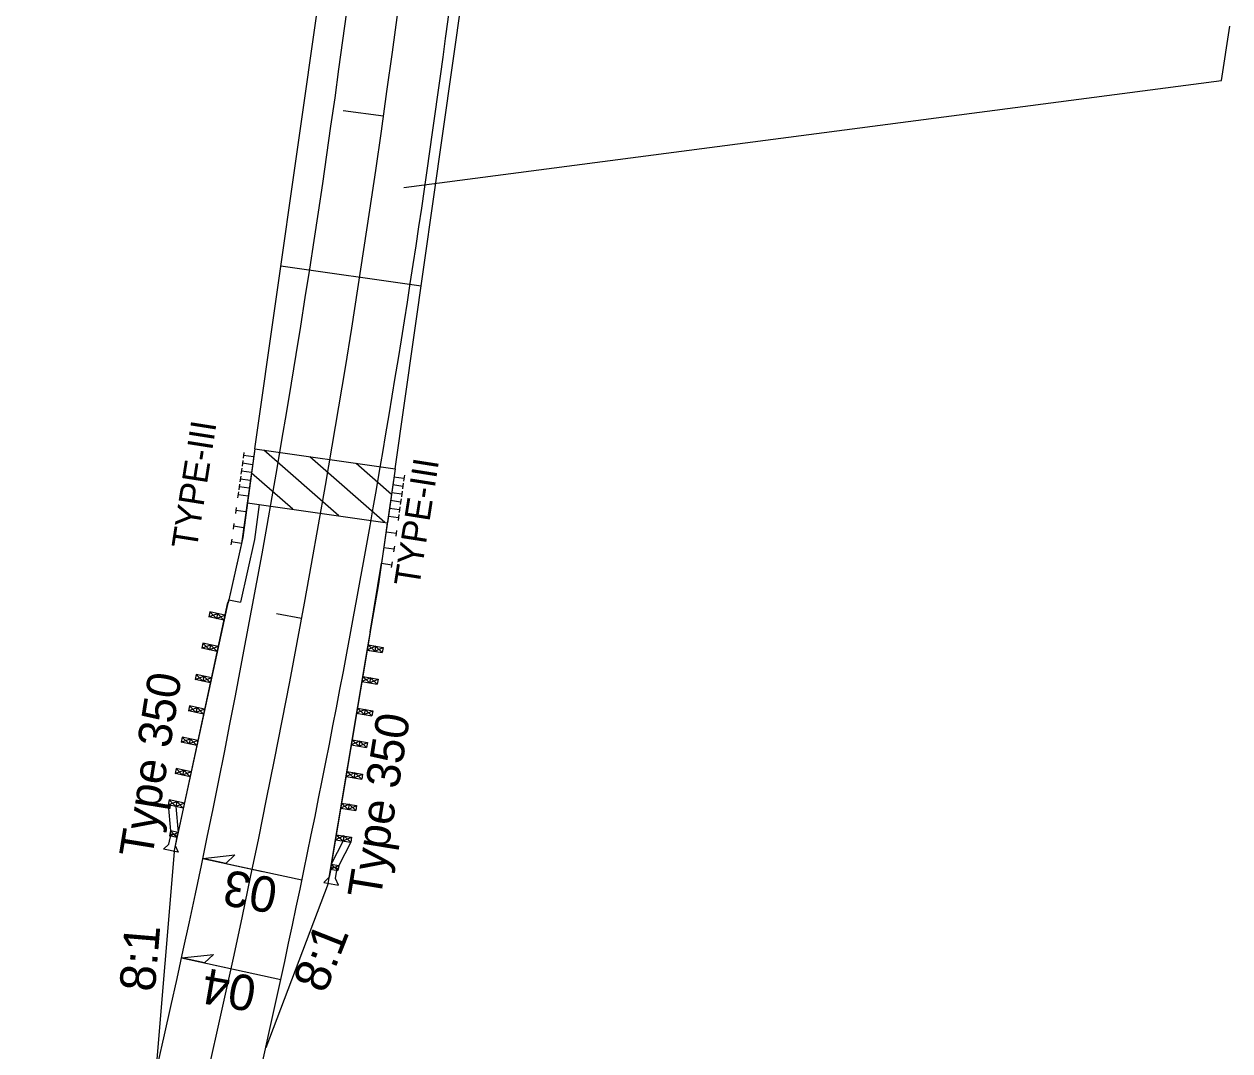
# Model space of a CAD drawing. Extents: x 1698814 to 1699654, y 708133 to 709468.
# Drawn here: x 1699331.8 to 1699568.8, y 708558.2 to 708760.1 of the extents above; entities that cross this region are included whole.
import ezdxf

# ---------------------------------------------------------------- set-up
doc = ezdxf.new("R2010")
doc.units = 0
for name, color, linetype in [('Prop Approach Slab', 7, 'Continuous'), ('Prop Approach Slab Hatching', 7, 'Continuous'), ('Prop Conc Shoulder Berm Gutter', 7, 'Continuous'), ('Prop Dimension', 7, 'Continuous'), ('Prop EOT', 7, 'Continuous'), ('Prop Guardrail', 7, 'Continuous'), ('Prop Guardrail Anchor Unit CELL', 7, 'Continuous'), ('Prop Horizontal Alignment', 7, 'Continuous'), ('Prop Horizontal Alignment Tick Large', 7, 'Continuous'), ('Prop Horizontal Alignment Tick Small', 7, 'Continuous'), ('Prop Paved Shoulder', 7, 'Continuous'), ('Prop Roadway Bridge', 7, 'Continuous'), ('Prop Structure Anchor Unit CELL', 7, 'Continuous'), ('Prop Superelevation  Arrow CELL', 7, 'Continuous'), ('Prop Superelevation Label', 7, 'Continuous')]:
    doc.layers.add(name, color=color, linetype=linetype)

msp = doc.modelspace()

# ---------------------------------------------------------------- linework, layer by layer
at = {"layer": 'Prop Approach Slab'}
for p, q in [((1699377.2, 708676.53), (1699375.7, 708665.94)), ((1699404.76, 708672.62), (1699403.26, 708662.03)), ((1699375.7, 708665.94), (1699403.26, 708662.03))]:
    msp.add_line(p, q, dxfattribs=at)
at = {"layer": 'Prop Approach Slab Hatching'}
for p, q in [((1699393.66, 708663.39), (1699378.96, 708676.28)), ((1699402.72, 708662.11), (1699388.01, 708674.99)), ((1699404.05, 708667.59), (1699397.06, 708673.71)), ((1699384.61, 708664.68), (1699376.52, 708671.76))]:
    msp.add_line(p, q, dxfattribs=at)
at = {"layer": 'Prop Conc Shoulder Berm Gutter'}
for p, q in [((1699375.73, 708665.94), (1699374.79, 708659.14)), ((1699402.98, 708660.05), (1699403.26, 708662.03)), ((1699374.79, 708659.14), (1699372.08, 708646.9)), ((1699372.08, 708646.9), (1699372.05, 708646.78))]:
    msp.add_line(p, q, dxfattribs=at)
at = {"layer": 'Prop Dimension'}
for p, q in [((1699567.1, 708748.96), (1699568.78, 708759.65)), ((1699406.45, 708727.92), (1699567.1, 708748.96))]:
    msp.add_line(p, q, dxfattribs=at)
at = {"layer": 'Prop EOT'}
for centre, radius, start, end in [((1697124.94, 709062.69), 2310, 350.26654, 356.20849), ((1697132.82, 709061.2), 2282.04, 344.49766, 353.61848), ((1697124.94, 709062.69), 2310, 344.49666, 350.26654)]:
    msp.add_arc(centre, radius, start, end, dxfattribs=at)
at = {"layer": 'Prop Guardrail'}
for p, q in [((1699374.53, 708657.97), (1699371.9, 708646.32)), ((1699399.84, 708640.51), (1699402.09, 708654.06))]:
    msp.add_line(p, q, dxfattribs=at)
at = {"layer": 'Prop Guardrail Anchor Unit CELL'}
for p, q in [((1699371.83, 708646.34), (1699361.98, 708600.64)), ((1699368.36, 708644.49), (1699368.15, 708643.51)), ((1699368.15, 708643.51), (1699369.83, 708644.17)), ((1699371.29, 708643.85), (1699368.36, 708644.49)), ((1699369.62, 708643.19), (1699368.36, 708644.49)), ((1699369.83, 708644.17), (1699369.62, 708643.19)), ((1699369.62, 708643.19), (1699371.29, 708643.85)), ((1699369.83, 708644.17), (1699371.08, 708642.88)), ((1699371.29, 708643.85), (1699371.08, 708642.88)), ((1699371.08, 708642.88), (1699368.15, 708643.51)), ((1699371.08, 708642.88), (1699369.62, 708643.19)), ((1699399.84, 708640.51), (1699392.11, 708594.4)), ((1699366.98, 708638.34), (1699366.77, 708637.36)), ((1699366.77, 708637.36), (1699368.47, 708638.02)), ((1699369.76, 708636.72), (1699366.77, 708637.36)), ((1699369.97, 708637.69), (1699366.98, 708638.34)), ((1699368.26, 708637.04), (1699366.98, 708638.34)), ((1699368.47, 708638.02), (1699368.26, 708637.04)), ((1699369.97, 708637.69), (1699368.26, 708637.04)), ((1699368.47, 708638.02), (1699369.76, 708636.72)), ((1699399.42, 708638), (1699399.26, 708637.01)), ((1699400.9, 708637.75), (1699399.26, 708637.01)), ((1699399.26, 708637.01), (1699402.21, 708636.52)), ((1699399.26, 708637.01), (1699400.74, 708636.77)), ((1699399.42, 708638), (1699402.38, 708637.5)), ((1699400.74, 708636.77), (1699399.42, 708638)), ((1699400.9, 708637.75), (1699400.74, 708636.77)), ((1699400.74, 708636.77), (1699402.38, 708637.5)), ((1699402.21, 708636.52), (1699400.9, 708637.75)), ((1699402.38, 708637.5), (1699402.21, 708636.52)), ((1699365.66, 708632.18), (1699365.45, 708631.2)), ((1699365.45, 708631.2), (1699367.15, 708631.86)), ((1699368.64, 708631.53), (1699365.66, 708632.18)), ((1699366.94, 708630.88), (1699365.66, 708632.18)), ((1699367.15, 708631.86), (1699366.94, 708630.88)), ((1699367.15, 708631.86), (1699368.43, 708630.56)), ((1699368.43, 708630.56), (1699365.45, 708631.2)), ((1699368.64, 708631.53), (1699366.94, 708630.88)), ((1699399.89, 708631.53), (1699398.21, 708630.8)), ((1699398.21, 708630.8), (1699401.23, 708630.29)), ((1699398.38, 708631.79), (1699401.39, 708631.28)), ((1699398.38, 708631.79), (1699399.72, 708630.55)), ((1699399.89, 708631.53), (1699399.72, 708630.55)), ((1699399.72, 708630.55), (1699401.39, 708631.28)), ((1699401.23, 708630.29), (1699399.89, 708631.53)), ((1699401.39, 708631.28), (1699401.23, 708630.29)), ((1699364.34, 708626.01), (1699364.13, 708625.04)), ((1699364.13, 708625.04), (1699365.83, 708625.69)), ((1699367.1, 708624.4), (1699364.13, 708625.04)), ((1699367.31, 708625.37), (1699364.34, 708626.01)), ((1699365.61, 708624.72), (1699364.34, 708626.01)), ((1699365.83, 708625.69), (1699365.61, 708624.72)), ((1699367.31, 708625.37), (1699365.61, 708624.72)), ((1699365.83, 708625.69), (1699367.1, 708624.4)), ((1699367.31, 708625.37), (1699367.1, 708624.4)), ((1699398.84, 708625.32), (1699397.17, 708624.58)), ((1699397.34, 708625.57), (1699400.34, 708625.07)), ((1699397.34, 708625.57), (1699398.68, 708624.33)), ((1699398.84, 708625.32), (1699398.68, 708624.33)), ((1699398.68, 708624.33), (1699400.34, 708625.07)), ((1699400.18, 708624.08), (1699398.84, 708625.32)), ((1699400.34, 708625.07), (1699400.18, 708624.08)), ((1699397.17, 708624.58), (1699400.18, 708624.08)), ((1699362.91, 708619.88), (1699362.7, 708618.9)), ((1699362.7, 708618.9), (1699364.45, 708619.55)), ((1699365.77, 708618.24), (1699362.7, 708618.9)), ((1699365.98, 708619.22), (1699362.91, 708619.88)), ((1699364.24, 708618.57), (1699362.91, 708619.88)), ((1699364.45, 708619.55), (1699364.24, 708618.57)), ((1699365.98, 708619.22), (1699364.24, 708618.57)), ((1699364.45, 708619.55), (1699365.77, 708618.24)), ((1699396.3, 708619.36), (1699396.13, 708618.37)), ((1699397.79, 708619.1), (1699396.13, 708618.37)), ((1699396.13, 708618.37), (1699399.13, 708617.87)), ((1699396.3, 708619.36), (1699399.29, 708618.85)), ((1699396.3, 708619.36), (1699397.63, 708618.12)), ((1699397.79, 708619.1), (1699397.63, 708618.12)), ((1699397.63, 708618.12), (1699399.29, 708618.85)), ((1699399.13, 708617.87), (1699397.79, 708619.1)), ((1699399.29, 708618.85), (1699399.13, 708617.87)), ((1699361.72, 708613.69), (1699361.51, 708612.71)), ((1699361.51, 708612.71), (1699363.19, 708613.37)), ((1699364.65, 708613.06), (1699361.72, 708613.69)), ((1699362.98, 708612.39), (1699361.72, 708613.69)), ((1699363.19, 708613.37), (1699362.98, 708612.39)), ((1699364.65, 708613.06), (1699362.98, 708612.39)), ((1699363.19, 708613.37), (1699364.44, 708612.08)), ((1699395.26, 708613.14), (1699398.35, 708612.62)), ((1699395.26, 708613.14), (1699396.64, 708611.9)), ((1699364.44, 708612.08), (1699361.51, 708612.71)), ((1699396.8, 708612.88), (1699395.09, 708612.16)), ((1699395.09, 708612.16), (1699398.18, 708611.64)), ((1699396.8, 708612.88), (1699396.64, 708611.9)), ((1699396.64, 708611.9), (1699398.35, 708612.62)), ((1699398.18, 708611.64), (1699396.8, 708612.88)), ((1699398.35, 708612.62), (1699398.18, 708611.64)), ((1699360.33, 708607.54), (1699360.12, 708606.56)), ((1699360.12, 708606.56), (1699361.83, 708607.22)), ((1699363.12, 708605.92), (1699360.12, 708606.56)), ((1699360.12, 708606.56), (1699360.62, 708601.44)), ((1699363.33, 708606.9), (1699360.33, 708607.54)), ((1699361.62, 708606.24), (1699360.33, 708607.54)), ((1699361.83, 708607.22), (1699361.62, 708606.24)), ((1699363.33, 708606.9), (1699361.62, 708606.24)), ((1699361.62, 708606.24), (1699362.08, 708601.13)), ((1699361.83, 708607.22), (1699363.12, 708605.92)), ((1699395.69, 708606.68), (1699394.05, 708605.94)), ((1699394.05, 708605.94), (1699397.01, 708605.44)), ((1699394.21, 708606.93), (1699397.17, 708606.43)), ((1699394.21, 708606.93), (1699395.53, 708605.69)), ((1699395.69, 708606.68), (1699395.53, 708605.69)), ((1699395.53, 708605.69), (1699397.17, 708606.43)), ((1699397.01, 708605.44), (1699395.69, 708606.68)), ((1699397.17, 708606.43), (1699397.01, 708605.44)), ((1699360.62, 708601.44), (1699360.41, 708600.47)), ((1699360.41, 708600.47), (1699362.08, 708601.13)), ((1699360.62, 708601.44), (1699360.51, 708600.95)), ((1699362.08, 708601.13), (1699360.62, 708601.44)), ((1699361.87, 708600.15), (1699360.62, 708601.44)), ((1699359.23, 708597.86), (1699360.3, 708598.85)), ((1699360.3, 708598.85), (1699360.7, 708600.86)), ((1699361.87, 708600.15), (1699360.41, 708600.47)), ((1699360.7, 708600.86), (1699361.3, 708600.74)), ((1699361.3, 708600.74), (1699361.9, 708600.62)), ((1699361.9, 708600.62), (1699361.5, 708598.61)), ((1699394.52, 708599.47), (1699392.2, 708594.89)), ((1699394.68, 708600.46), (1699393.01, 708599.73)), ((1699393.01, 708599.73), (1699396.03, 708599.22)), ((1699393.17, 708600.71), (1699396.19, 708600.21)), ((1699393.17, 708600.71), (1699394.52, 708599.47)), ((1699396.03, 708599.22), (1699393.68, 708594.64)), ((1699394.68, 708600.46), (1699394.52, 708599.47)), ((1699394.52, 708599.47), (1699396.19, 708600.21)), ((1699396.03, 708599.22), (1699394.68, 708600.46)), ((1699396.19, 708600.21), (1699396.03, 708599.22)), ((1699362.12, 708597.29), (1699359.23, 708597.86)), ((1699361.5, 708598.61), (1699362.12, 708597.29)), ((1699392.18, 708594.35), (1699391.81, 708592.34)), ((1699392.03, 708593.91), (1699393.68, 708594.64)), ((1699392.78, 708594.24), (1699392.18, 708594.35)), ((1699392.2, 708594.89), (1699393.68, 708594.64)), ((1699393.51, 708593.66), (1699392.2, 708594.89)), ((1699393.38, 708594.13), (1699392.78, 708594.24)), ((1699393.01, 708592.12), (1699393.38, 708594.13)), ((1699393.68, 708594.64), (1699393.51, 708593.66)), ((1699393.68, 708594.64), (1699393.59, 708594.15)), ((1699391.81, 708592.34), (1699390.75, 708591.34)), ((1699392.03, 708593.91), (1699393.51, 708593.66)), ((1699393.64, 708590.8), (1699393.01, 708592.12)), ((1699390.75, 708591.34), (1699393.64, 708590.8))]:
    msp.add_line(p, q, dxfattribs=at)
at = {"layer": 'Prop Horizontal Alignment'}
msp.add_arc((1697124.94, 709062.69), 2300, 343.70663, 356.20849, dxfattribs=at)
at = {"layer": 'Prop Horizontal Alignment Tick Large'}
msp.add_line((1699402.46, 708741.93), (1699394.54, 708743.04), dxfattribs=at)
at = {"layer": 'Prop Horizontal Alignment Tick Small'}
msp.add_line((1699386.37, 708643.24), (1699381.45, 708644.15), dxfattribs=at)
at = {"layer": 'Prop Paved Shoulder'}
for p, q in [((1699398.84, 708717.19), (1699398.84, 708717.19)), ((1699378.03, 708665.61), (1699377.08, 708658.73)), ((1699377.08, 708658.73), (1699374.35, 708646.4)), ((1699401.55, 708650.01), (1699402.98, 708660.05)), ((1699399.36, 708637.66), (1699401.55, 708650.01)), ((1699361.34, 708597.31), (1699372.08, 708646.9)), ((1699372.08, 708646.9), (1699374.35, 708646.41)), ((1699391.56, 708591.14), (1699399.36, 708637.66)), ((1699361.34, 708597.31), (1699357.64, 708553.41)), ((1699391.56, 708591.14), (1699379.31, 708558.8))]:
    msp.add_line(p, q, dxfattribs=at)
at = {"layer": 'Prop Roadway Bridge'}
for p, q in [((1699377.2, 708676.53), (1699397.2, 708817.65)), ((1699404.76, 708672.62), (1699424.76, 708813.74)), ((1699409.85, 708708.57), (1699382.3, 708712.47)), ((1699377.16, 708676.53), (1699404.72, 708672.63))]:
    msp.add_line(p, q, dxfattribs=at)
at = {"layer": 'Prop Structure Anchor Unit CELL'}
for p, q in [((1699377.16, 708676.53), (1699374.53, 708657.97)), ((1699375.04, 708675.83), (1699374.88, 708674.7)), ((1699376.94, 708674.99), (1699374.96, 708675.27)), ((1699374.61, 708672.74), (1699374.45, 708671.6)), ((1699376.51, 708671.89), (1699374.53, 708672.17)), ((1699374.83, 708674.29), (1699374.66, 708673.15)), ((1699376.72, 708673.44), (1699374.74, 708673.72)), ((1699404.72, 708672.63), (1699402.09, 708654.06)), ((1699374.39, 708671.19), (1699374.23, 708670.06)), ((1699376.29, 708670.34), (1699374.31, 708670.62)), ((1699404.5, 708671.08), (1699406.48, 708670.8)), ((1699406.34, 708669.82), (1699406.18, 708668.68)), ((1699406.56, 708671.37), (1699406.4, 708670.23)), ((1699373.95, 708668.1), (1699373.79, 708666.96)), ((1699375.85, 708667.25), (1699373.87, 708667.53)), ((1699374.17, 708669.64), (1699374.01, 708668.51)), ((1699376.07, 708668.8), (1699374.09, 708669.08)), ((1699404.06, 708667.99), (1699406.04, 708667.7)), ((1699404.28, 708669.53), (1699406.26, 708669.25)), ((1699406.12, 708668.27), (1699405.96, 708667.14)), ((1699403.84, 708666.44), (1699405.82, 708666.16)), ((1699405.69, 708665.18), (1699405.52, 708664.04)), ((1699405.9, 708666.72), (1699405.74, 708665.59)), ((1699373.51, 708665), (1699373.35, 708663.87)), ((1699375.41, 708664.16), (1699373.43, 708664.44)), ((1699403.41, 708663.34), (1699405.39, 708663.06)), ((1699403.62, 708664.89), (1699405.6, 708664.61)), ((1699405.47, 708663.63), (1699405.31, 708662.5)), ((1699373.07, 708661.91), (1699372.91, 708660.78)), ((1699374.97, 708661.06), (1699372.99, 708661.34)), ((1699405.03, 708660.54), (1699404.87, 708659.4)), ((1699372.63, 708658.82), (1699372.47, 708657.68)), ((1699374.53, 708657.97), (1699372.55, 708658.25)), ((1699402.97, 708660.25), (1699404.95, 708659.97)), ((1699402.53, 708657.16), (1699404.51, 708656.88)), ((1699404.59, 708657.44), (1699404.43, 708656.31)), ((1699402.09, 708654.06), (1699404.07, 708653.78)), ((1699404.15, 708654.35), (1699403.99, 708653.21))]:
    msp.add_line(p, q, dxfattribs=at)
at = {"layer": 'Prop Superelevation  Arrow CELL'}
for p, q in [((1699366.95, 708596.05), (1699378.67, 708593.5)), ((1699362.78, 708576.49), (1699374.51, 708573.94))]:
    msp.add_line(p, q, dxfattribs=at)
for points in [[(1699366.95, 708596.05), (1699373.23, 708596.73), (1699371.47, 708595.07)], [(1699362.78, 708576.49), (1699369.07, 708577.17), (1699367.3, 708575.51)]]:
    msp.add_lwpolyline(points, close=True, dxfattribs=at)
at = {"layer": 'Prop Superelevation Label'}
for p, q in [((1699366.95, 708596.05), (1699386.44, 708591.82)), ((1699362.78, 708576.49), (1699382.26, 708572.26))]:
    msp.add_line(p, q, dxfattribs=at)

# ---------------------------------------------------------------- texts
at = {"layer": 'Prop Dimension'}
for s, height, rotation, p in [('Type 350', 6.562, 80.7477, (1699356.96, 708595.87)), ('Type 350', 6.562, 80.7477, (1699401.83, 708587.88)), ('8:1', 7, 85.2292, (1699357.51, 708569.7)), ('8:1', 7, 68.4512, (1699390.99, 708569.29))]:
    msp.add_text(s, height=height, rotation=rotation, dxfattribs=at).set_placement(p)
at = {"layer": 'Prop Structure Anchor Unit CELL'}
for p in [(1699365.73, 708656.66), (1699409.45, 708649.28)]:
    msp.add_text('TYPE-III', height=5, rotation=81.0546, dxfattribs=at).set_placement(p)
at = {"layer": 'Prop Superelevation Label'}
for s, p in [('03', (1699381.98, 708592.06)), ('04', (1699377.82, 708572.73))]:
    msp.add_text(s, height=7, rotation=170.1291, dxfattribs=at).set_placement(p)

doc.saveas('drawing.dxf')
